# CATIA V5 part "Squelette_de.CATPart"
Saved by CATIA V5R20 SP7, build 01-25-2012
Part number: Squelette_de
Publications: "Plan.2", "Droite.5", "Droite.6"
Bounding box of the stored display mesh (mm): x 0 to 20, y -30.568 to 18.055, z 48.567 to 60.222
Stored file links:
  G:\bon\Nouveau dossier\Squelette_de.CATPart
  C:\Documents and Settings\cgirerd\Bureau\Copie de Copie de Nouveau dossier\765.CATProduct
  G:\bon\Nouveau dossier\mecanism.skl.CATProduct
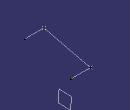
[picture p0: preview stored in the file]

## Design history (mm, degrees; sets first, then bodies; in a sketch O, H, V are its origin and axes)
Set1
  Point1 "D": linked copy from another document
  Point2 "E": linked copy from another document
  Plane1: linked copy from another document
Set2
  Line1: type PtPt, FirstPoint Point1, SecondPoint Point2
  Line2: type Normal, RefPoint Point1, RefSkin Plane1, Start 0, End 20
  Line3: type Normal, RefPoint Point2, RefSkin Plane1, Start 0, End 20
Body1 (main body)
